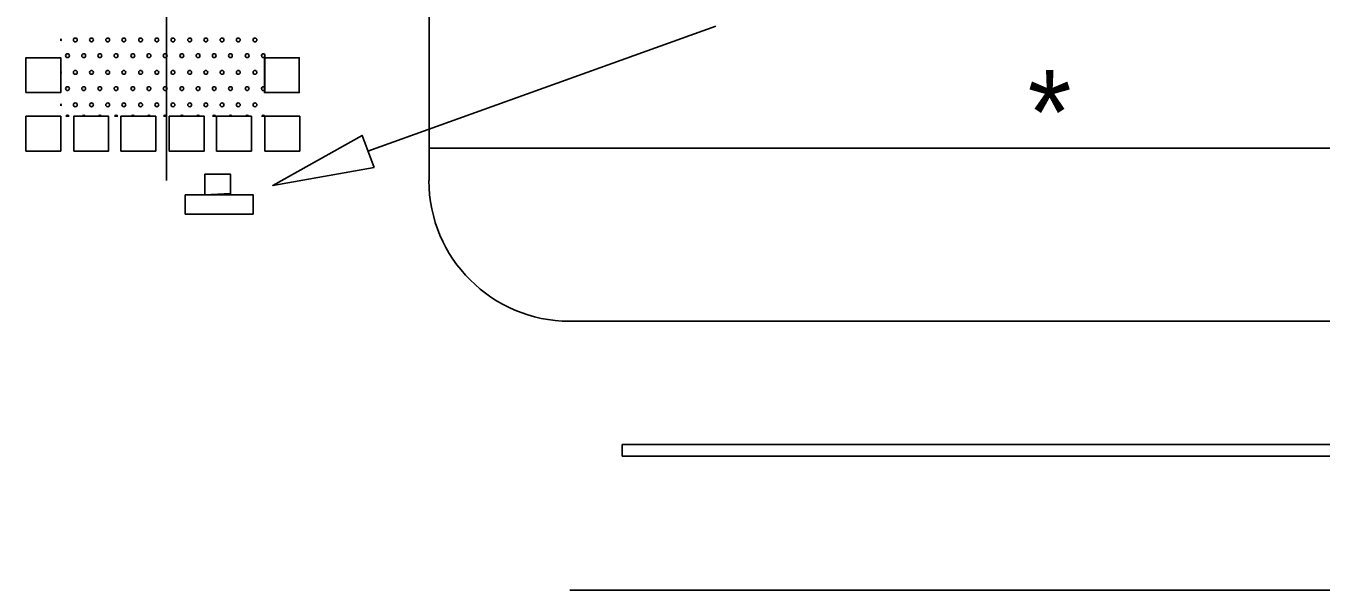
# Model space of a CAD drawing. Extents: x 1531.4 to 1538.6, y 1528.5 to 1539.8.
# Drawn here: x 1534.733 to 1536.717, y 1535.949 to 1536.813 of the extents above; entities that cross this region are included whole.
import ezdxf

# ---------------------------------------------------------------- set-up
doc = ezdxf.new("R2010")
doc.units = 0
for name, color, linetype in [('DETL-DIMS', 7, 'Continuous'), ('DETL-LINE', 7, 'Continuous'), ('DETL-NOTE', 7, 'Continuous'), ('USER-BORD', 7, 'Continuous')]:
    doc.layers.add(name, color=color, linetype=linetype)

# ---------------------------------------------------------------- blocks, each defined once
blk = doc.blocks.new('CD2')
at = {"layer": 'USER-BORD'}
blk.add_lwpolyline([(-0.0062, -0.0062), (0, -0.0062), (0, 0), (-0.0062, 0)], close=True, dxfattribs=at)
blk = doc.blocks.new('SIGN')
at = {"layer": 'USER-BORD'}
for points in [[(-0.0013, 0.0018), (0.0011, 0.0019), (0.0011, 0.0037), (-0.0013, 0.0037)], [(-0.0031, 0.0018), (-0.0031, 0), (0.0032, 0), (0.0032, 0.0018)]]:
    blk.add_lwpolyline(points, close=True, dxfattribs=at)

msp = doc.modelspace()

# ---------------------------------------------------------------- linework, layer by layer
at = {"layer": 'DETL-DIMS'}
for p, q in [((1535.2564, 1536.6213), (1535.7896, 1536.8124)), ((1535.3511, 1536.6255), (1537.1973, 1536.6255))]:
    msp.add_line(p, q, dxfattribs=at)
msp.add_lwpolyline([(1535.2659, 1536.5962), (1535.2477, 1536.6453), (1535.1108, 1536.5686)], close=True, dxfattribs=at)
at = {"layer": 'DETL-LINE'}
for p, q in [((1534.948, 1539.1023), (1534.948, 1536.5764)), ((1535.3502, 1539.1023), (1535.3502, 1536.5764)), ((1534.948, 1537.1019), (1534.948, 1536.6746)), ((1534.8083, 1536.7914), (1534.8083, 1536.7914)), ((1534.8083, 1536.7914), (1534.8083, 1536.7914)), ((1534.8331, 1536.7914), (1534.8331, 1536.7914)), ((1534.8331, 1536.7914), (1534.8331, 1536.7914)), ((1534.8579, 1536.7914), (1534.8579, 1536.7914)), ((1534.8579, 1536.7914), (1534.8579, 1536.7914)), ((1534.8827, 1536.7914), (1534.8827, 1536.7914)), ((1534.8827, 1536.7914), (1534.8827, 1536.7914)), ((1534.9083, 1536.7914), (1534.9083, 1536.7914)), ((1534.9083, 1536.7914), (1534.9083, 1536.7914)), ((1534.9331, 1536.7914), (1534.9331, 1536.7914)), ((1534.9331, 1536.7914), (1534.9331, 1536.7914)), ((1534.9579, 1536.7914), (1534.9579, 1536.7914)), ((1534.9579, 1536.7914), (1534.9579, 1536.7914)), ((1534.9835, 1536.7914), (1534.9835, 1536.7914)), ((1534.9835, 1536.7914), (1534.9835, 1536.7914)), ((1535.0083, 1536.7914), (1535.0083, 1536.7914)), ((1535.0083, 1536.7914), (1535.0083, 1536.7914)), ((1535.0331, 1536.7914), (1535.0331, 1536.7914)), ((1535.0331, 1536.7914), (1535.0331, 1536.7914)), ((1535.0579, 1536.7914), (1535.0579, 1536.7914)), ((1535.0579, 1536.7914), (1535.0579, 1536.7914)), ((1535.0835, 1536.7914), (1535.0835, 1536.7914)), ((1535.0835, 1536.7914), (1535.0835, 1536.7914)), ((1534.7955, 1536.7674), (1534.7955, 1536.7674)), ((1534.7963, 1536.7674), (1534.7963, 1536.7674)), ((1534.8203, 1536.7674), (1534.8203, 1536.7674)), ((1534.8211, 1536.7674), (1534.8211, 1536.7674)), ((1534.8459, 1536.7674), (1534.8459, 1536.7674)), ((1534.8459, 1536.7674), (1534.8459, 1536.7674)), ((1534.8707, 1536.7674), (1534.8707, 1536.7674)), ((1534.8707, 1536.7674), (1534.8707, 1536.7674)), ((1534.8955, 1536.7674), (1534.8955, 1536.7674)), ((1534.8963, 1536.7674), (1534.8963, 1536.7674)), ((1534.9203, 1536.7674), (1534.9203, 1536.7674)), ((1534.9211, 1536.7674), (1534.9211, 1536.7674)), ((1534.9459, 1536.7674), (1534.9459, 1536.7674)), ((1534.9459, 1536.7674), (1534.9459, 1536.7674)), ((1534.9707, 1536.7674), (1534.9707, 1536.7674)), ((1534.9715, 1536.7674), (1534.9715, 1536.7674)), ((1534.9955, 1536.7674), (1534.9955, 1536.7674)), ((1534.9963, 1536.7674), (1534.9963, 1536.7674)), ((1535.0203, 1536.7674), (1535.0203, 1536.7674)), ((1535.0211, 1536.7674), (1535.0211, 1536.7674)), ((1535.0459, 1536.7674), (1535.0459, 1536.7674)), ((1535.0459, 1536.7674), (1535.0459, 1536.7674)), ((1535.0707, 1536.7674), (1535.0707, 1536.7674)), ((1535.0715, 1536.7674), (1535.0715, 1536.7674)), ((1535.0955, 1536.7674), (1535.0955, 1536.7674)), ((1535.0963, 1536.7674), (1535.0963, 1536.7674)), ((1534.8083, 1536.7418), (1534.8083, 1536.7418)), ((1534.8331, 1536.7418), (1534.8331, 1536.7418)), ((1534.8579, 1536.7418), (1534.8579, 1536.7418)), ((1534.8827, 1536.7418), (1534.8827, 1536.7418)), ((1534.9083, 1536.7418), (1534.9083, 1536.7418)), ((1534.9331, 1536.7418), (1534.9331, 1536.7418)), ((1534.9579, 1536.7418), (1534.9579, 1536.7418)), ((1534.9835, 1536.7418), (1534.9835, 1536.7418)), ((1535.0083, 1536.7418), (1535.0083, 1536.7418)), ((1535.0331, 1536.7418), (1535.0331, 1536.7418)), ((1535.0579, 1536.7418), (1535.0579, 1536.7418)), ((1535.0835, 1536.7418), (1535.0835, 1536.7418)), ((1534.7955, 1536.717), (1534.7955, 1536.717)), ((1534.7963, 1536.717), (1534.7963, 1536.717)), ((1534.8203, 1536.717), (1534.8203, 1536.717)), ((1534.8211, 1536.717), (1534.8211, 1536.717)), ((1534.8459, 1536.717), (1534.8459, 1536.717)), ((1534.8459, 1536.717), (1534.8459, 1536.717)), ((1534.8707, 1536.717), (1534.8707, 1536.717)), ((1534.8707, 1536.717), (1534.8707, 1536.717)), ((1534.8955, 1536.717), (1534.8955, 1536.717)), ((1534.8963, 1536.717), (1534.8963, 1536.717)), ((1534.9203, 1536.717), (1534.9203, 1536.717)), ((1534.9211, 1536.717), (1534.9211, 1536.717)), ((1534.9459, 1536.717), (1534.9459, 1536.717)), ((1534.9459, 1536.717), (1534.9459, 1536.717)), ((1534.9707, 1536.717), (1534.9707, 1536.717)), ((1534.9715, 1536.717), (1534.9715, 1536.717)), ((1534.9955, 1536.717), (1534.9955, 1536.717)), ((1534.9963, 1536.717), (1534.9963, 1536.717)), ((1535.0203, 1536.717), (1535.0203, 1536.717)), ((1535.0211, 1536.717), (1535.0211, 1536.717)), ((1535.0459, 1536.717), (1535.0459, 1536.717)), ((1535.0459, 1536.717), (1535.0459, 1536.717)), ((1535.0707, 1536.717), (1535.0707, 1536.717)), ((1535.0715, 1536.717), (1535.0715, 1536.717)), ((1535.0955, 1536.717), (1535.0955, 1536.717)), ((1535.0963, 1536.717), (1535.0963, 1536.717)), ((1534.8083, 1536.6922), (1534.8083, 1536.6922)), ((1534.8083, 1536.6922), (1534.8083, 1536.6922)), ((1534.8331, 1536.6922), (1534.8331, 1536.6922)), ((1534.8331, 1536.6922), (1534.8331, 1536.6922)), ((1534.8579, 1536.6922), (1534.8579, 1536.6922)), ((1534.8579, 1536.6922), (1534.8579, 1536.6922)), ((1534.8827, 1536.6922), (1534.8827, 1536.6922)), ((1534.8827, 1536.6922), (1534.8827, 1536.6922)), ((1534.9083, 1536.6922), (1534.9083, 1536.6922)), ((1534.9083, 1536.6922), (1534.9083, 1536.6922)), ((1534.9331, 1536.6922), (1534.9331, 1536.6922)), ((1534.9331, 1536.6922), (1534.9331, 1536.6922)), ((1534.9579, 1536.6922), (1534.9579, 1536.6922)), ((1534.9579, 1536.6922), (1534.9579, 1536.6922)), ((1534.9835, 1536.6922), (1534.9835, 1536.6922)), ((1534.9835, 1536.6922), (1534.9835, 1536.6922)), ((1535.0083, 1536.6922), (1535.0083, 1536.6922)), ((1535.0083, 1536.6922), (1535.0083, 1536.6922)), ((1535.0331, 1536.6922), (1535.0331, 1536.6922)), ((1535.0331, 1536.6922), (1535.0331, 1536.6922)), ((1535.0579, 1536.6922), (1535.0579, 1536.6922)), ((1535.0579, 1536.6922), (1535.0579, 1536.6922)), ((1535.0835, 1536.6922), (1535.0835, 1536.6922)), ((1535.0835, 1536.6922), (1535.0835, 1536.6922)), ((1535.0988, 1536.6746), (1535.0988, 1536.6747)), ((1537.2377, 1536.361), (1535.5657, 1536.361)), ((1535.6458, 1536.1723), (1537.2377, 1536.1723)), ((1535.6458, 1536.1723), (1535.6458, 1536.1542)), ((1535.6458, 1536.1542), (1537.2377, 1536.1542)), ((1537.2377, 1535.9492), (1535.5657, 1535.9492))]:
    msp.add_line(p, q, dxfattribs=at)
for points in [[(1534.786, 1536.7929), (1534.786, 1536.7898)], [(1535.0988, 1536.7642), (1535.0979, 1536.7642), (1535.0979, 1536.7108), (1535.0988, 1536.7108)], [(1535.0988, 1536.7658), (1535.0988, 1536.7688)], [(1535.0988, 1536.7108), (1535.0988, 1536.7642)], [(1534.786, 1536.7432), (1534.786, 1536.7402)], [(1535.0988, 1536.7154), (1535.0988, 1536.7184)], [(1534.786, 1536.6936), (1534.786, 1536.6906)], [(1534.7937, 1536.6746), (1534.7988, 1536.6746)], [(1534.8185, 1536.6746), (1534.8236, 1536.6746)], [(1534.8433, 1536.6746), (1534.8484, 1536.6746)], [(1534.8681, 1536.6746), (1534.8732, 1536.6746)], [(1534.8937, 1536.6746), (1534.8988, 1536.6746)], [(1534.9185, 1536.6746), (1534.9236, 1536.6746)], [(1534.9433, 1536.6746), (1534.9484, 1536.6746)], [(1534.9689, 1536.6746), (1534.974, 1536.6746)], [(1534.9937, 1536.6746), (1534.9988, 1536.6746)], [(1535.0185, 1536.6746), (1535.0236, 1536.6746)], [(1535.0433, 1536.6746), (1535.0484, 1536.6746)], [(1535.0689, 1536.6746), (1535.074, 1536.6746)], [(1535.0937, 1536.6746), (1535.0988, 1536.6746)]]:
    msp.add_lwpolyline(points, dxfattribs=at)
for centre in [(1534.8083, 1536.7914), (1534.8331, 1536.7914), (1534.8579, 1536.7914), (1534.8827, 1536.7914), (1534.9083, 1536.7914), (1534.9331, 1536.7914), (1534.9579, 1536.7914), (1534.9835, 1536.7914), (1535.0083, 1536.7914), (1535.0331, 1536.7914), (1535.0579, 1536.7914), (1535.0835, 1536.7914), (1534.7963, 1536.7673), (1534.8211, 1536.7673), (1534.8459, 1536.7673), (1534.8707, 1536.7673), (1534.8963, 1536.7673), (1534.9211, 1536.7673), (1534.9459, 1536.7673), (1534.9715, 1536.7673), (1534.9963, 1536.7673), (1535.0211, 1536.7673), (1535.0459, 1536.7673), (1535.0715, 1536.7673), (1534.8083, 1536.7417), (1534.8331, 1536.7417), (1534.8579, 1536.7417), (1534.8827, 1536.7417), (1534.9083, 1536.7417), (1534.9331, 1536.7417), (1534.9579, 1536.7417), (1534.9835, 1536.7417), (1535.0083, 1536.7417), (1535.0331, 1536.7417), (1535.0579, 1536.7417), (1535.0835, 1536.7417), (1534.7963, 1536.7169), (1534.8211, 1536.7169), (1534.8459, 1536.7169), (1534.8707, 1536.7169), (1534.8963, 1536.7169), (1534.9211, 1536.7169), (1534.9459, 1536.7169), (1534.9715, 1536.7169), (1534.9963, 1536.7169), (1535.0211, 1536.7169), (1535.0459, 1536.7169), (1535.0715, 1536.7169), (1534.8083, 1536.6921), (1534.8331, 1536.6921), (1534.8579, 1536.6921), (1534.8827, 1536.6921), (1534.9083, 1536.6921), (1534.9331, 1536.6921), (1534.9579, 1536.6921), (1534.9835, 1536.6921), (1535.0083, 1536.6921), (1535.0331, 1536.6921), (1535.0579, 1536.6921), (1535.0835, 1536.6921)]:
    msp.add_circle(centre, 0.00291, dxfattribs=at)
for centre, radius, start, end in [((1534.7835, 1536.7914), 0.00291, 328.8409, 31.1591), ((1535.0963, 1536.7673), 0.00291, 31.1591, 328.8409), ((1534.7835, 1536.7417), 0.00291, 328.8409, 31.1591), ((1535.0963, 1536.7169), 0.00291, 31.1591, 328.8409), ((1534.7835, 1536.6921), 0.00291, 328.8409, 31.1591), ((1534.7963, 1536.6732), 0.00291, 29.3703, 150.6297), ((1534.8211, 1536.6732), 0.00291, 29.3703, 150.6297), ((1534.8459, 1536.6732), 0.00291, 29.3703, 150.6297), ((1534.8707, 1536.6732), 0.00291, 29.3703, 150.6297), ((1534.8963, 1536.6732), 0.00291, 29.3703, 150.6297), ((1534.9211, 1536.6732), 0.00291, 29.3703, 150.6297), ((1534.9459, 1536.6732), 0.00291, 29.3703, 150.6297), ((1534.9715, 1536.6732), 0.00291, 29.3703, 150.6297), ((1534.9963, 1536.6732), 0.00291, 29.3703, 150.6297), ((1535.0211, 1536.6732), 0.00291, 29.3703, 150.6297), ((1535.0459, 1536.6732), 0.00291, 29.3703, 150.6297), ((1535.0715, 1536.6732), 0.00291, 29.3703, 150.6297), ((1535.0963, 1536.6732), 0.00291, 31.1591, 150.6297), ((1535.5654, 1536.5762), 0.2154, 180, 270)]:
    msp.add_arc(centre, radius, start, end, dxfattribs=at)

# ---------------------------------------------------------------- block references
for name, p, xscale, yscale in [('CD2', (1534.786, 1536.7642), 8.61495264, 8.61495264), ('CD2', (1535.1513, 1536.7642), 8.61495264, 8.61495264), ('CD2', (1534.786, 1536.6746), 8.61495264, 8.61495264), ('CD2', (1534.8593, 1536.6746), 8.61495264, 8.61495264), ('CD2', (1534.9316, 1536.6746), 8.61495264, 8.61495264), ('CD2', (1535.0057, 1536.6746), 8.61495264, 8.61495264), ('CD2', (1535.0781, 1536.6746), 8.61495264, 8.61495264), ('CD2', (1535.1522, 1536.6746), 8.61495264, 8.61495264), ('SIGN', (1535.0279, 1536.5248), 16.482020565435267, 16.482020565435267)]:
    msp.add_blockref(name, p, dxfattribs=dict(at, xscale=xscale, yscale=yscale))

# ---------------------------------------------------------------- texts
at = {"layer": 'DETL-NOTE'}
msp.add_text('*', height=0.1292, dxfattribs=at).set_placement((1536.2672, 1536.6161))

doc.saveas('drawing.dxf')
